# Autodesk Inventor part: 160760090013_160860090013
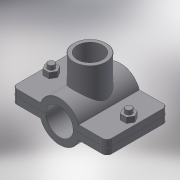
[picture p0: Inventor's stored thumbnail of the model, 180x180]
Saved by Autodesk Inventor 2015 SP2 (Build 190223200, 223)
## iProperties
Created: 2017-05
Part Number: 160760090013_160860090013
Material: Generic
Description: PLASSON SADDLE 90-1.1/4"
Document SubType Name: Modeling
Designer: KIM
Density: 1 g/cm^3
Appearance: Default
Author: KIM
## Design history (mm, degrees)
derived "16076.ipt"
feature "Solid1::16076.ipt"
feature "Solid2::16076.ipt"
tag "TaggingFeature1"
body "Solid1"
other parameters: "d0" = 99, "d1" = 141, "d2" = 45, "d4" = 105, "d5" = 0, "d6" = 7.05, "d7" = 141, "d8" = 0.1, "d10" = 0, "d11" = 0.9, "d14" = 50.6376, "d20" = 0.9, "d23" = 0.9, "d36" = 13, "d37" = 10.4, "d38" = 53, "d39" = 0, "d40" = 3, "d41" = 5, "d42" = 0, "d43" = 8, "d44" = 3, "d45" = 0, "d46" = 0.9, "d52" = 38.952, "d53" = 25, "d54" = 0, "d55" = 32, "d57" = 0, "d58" = 97.2, "d60" = 0, "d62" = 13, "d63" = 10.4, "d66" = 84.2, "B_" = 32, "G_" = 38.952, "L_" = 141, "L_1" = 105, "l_2" = 25
